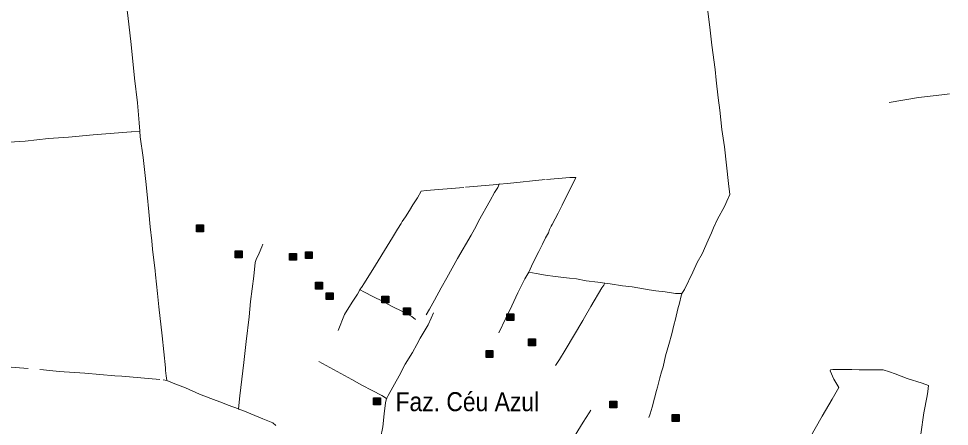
# Model space of a CAD drawing. Extents: x 393.5 to 446.9, y 8064.8 to 8120.4.
# Drawn here: x 425 to 432.83, y 8082.75 to 8086.18 of the extents above; entities that cross this region are included whole.
import ezdxf

# ---------------------------------------------------------------- set-up
doc = ezdxf.new("R2010")
doc.units = 0
doc.header["$LTSCALE"] = 0.064
doc.linetypes.add('DOT_DASHED', pattern=[7.7, 5, -1.2, 0.3, -1.2])
doc.layers.add('2', color=7, linetype='Continuous', lineweight=25)
doc.layers.add('22', color=7, linetype='DOT_DASHED', lineweight=13)
doc.layers.add('61', color=7, linetype='Continuous')

msp = doc.modelspace()

# ---------------------------------------------------------------- hatches: boundary and pattern name
at = {"layer": '2'}
for points in [[(426.4934, 8084.4448), (426.5514, 8084.4448), (426.5514, 8084.3868), (426.4934, 8084.3868)], [(426.8194, 8084.2253), (426.8774, 8084.2253), (426.8774, 8084.1673), (426.8194, 8084.1673)], [(427.4108, 8084.2181), (427.4688, 8084.2181), (427.4688, 8084.1601), (427.4108, 8084.1601)], [(427.278, 8084.2044), (427.336, 8084.2044), (427.336, 8084.1464), (427.278, 8084.1464)], [(427.4963, 8083.9617), (427.5543, 8083.9617), (427.5543, 8083.9037), (427.4963, 8083.9037)], [(427.5859, 8083.8732), (427.6439, 8083.8732), (427.6439, 8083.8152), (427.5859, 8083.8152)], [(428.0558, 8083.8447), (428.1138, 8083.8447), (428.1138, 8083.7867), (428.0558, 8083.7867)], [(428.2381, 8083.746), (428.2961, 8083.746), (428.2961, 8083.688), (428.2381, 8083.688)], [(429.1079, 8083.6957), (429.1659, 8083.6957), (429.1659, 8083.6377), (429.1079, 8083.6377)], [(429.2902, 8083.4845), (429.3482, 8083.4845), (429.3482, 8083.4265), (429.2902, 8083.4265)], [(428.9324, 8083.3864), (428.9904, 8083.3864), (428.9904, 8083.3284), (428.9324, 8083.3284)], [(427.9852, 8082.9864), (428.0432, 8082.9864), (428.0432, 8082.9284), (427.9852, 8082.9284)], [(429.9762, 8082.9605), (430.0342, 8082.9605), (430.0342, 8082.9025), (429.9762, 8082.9025)], [(430.5006, 8082.8458), (430.5586, 8082.8458), (430.5586, 8082.7878), (430.5006, 8082.7878)]]:
    msp.add_hatch(color=256, dxfattribs=at).paths.add_polyline_path(points)

# ---------------------------------------------------------------- linework, layer by layer
for points in [[(426.4934, 8084.4448), (426.5514, 8084.4448), (426.5514, 8084.3868), (426.4934, 8084.3868)], [(426.8194, 8084.2253), (426.8774, 8084.2253), (426.8774, 8084.1673), (426.8194, 8084.1673)], [(427.4108, 8084.2181), (427.4688, 8084.2181), (427.4688, 8084.1601), (427.4108, 8084.1601)], [(427.278, 8084.2044), (427.336, 8084.2044), (427.336, 8084.1464), (427.278, 8084.1464)], [(427.4963, 8083.9617), (427.5543, 8083.9617), (427.5543, 8083.9037), (427.4963, 8083.9037)], [(427.5859, 8083.8732), (427.6439, 8083.8732), (427.6439, 8083.8152), (427.5859, 8083.8152)], [(428.0558, 8083.8447), (428.1138, 8083.8447), (428.1138, 8083.7867), (428.0558, 8083.7867)], [(428.2381, 8083.746), (428.2961, 8083.746), (428.2961, 8083.688), (428.2381, 8083.688)], [(429.1079, 8083.6957), (429.1659, 8083.6957), (429.1659, 8083.6377), (429.1079, 8083.6377)], [(429.2902, 8083.4845), (429.3482, 8083.4845), (429.3482, 8083.4265), (429.2902, 8083.4265)], [(428.9324, 8083.3864), (428.9904, 8083.3864), (428.9904, 8083.3284), (428.9324, 8083.3284)], [(427.9852, 8082.9864), (428.0432, 8082.9864), (428.0432, 8082.9284), (427.9852, 8082.9284)], [(429.9762, 8082.9605), (430.0342, 8082.9605), (430.0342, 8082.9025), (429.9762, 8082.9025)], [(430.5006, 8082.8458), (430.5586, 8082.8458), (430.5586, 8082.7878), (430.5006, 8082.7878)]]:
    msp.add_lwpolyline(points, close=True, dxfattribs=at)
at = {"layer": '22'}
for points in [[(426.0169, 8085.2329), (426.0107, 8085.3049), (425.9956, 8085.4717), (425.9715, 8085.681), (425.9428, 8085.9657), (425.9141, 8086.2093), (425.8809, 8086.4984), (425.8628, 8086.6096), (425.8553, 8086.6857), (425.8419, 8086.8395), (425.8376, 8086.8682)], [(430.5821, 8083.8659), (430.6038, 8083.9012), (430.6748, 8084.0471), (430.7111, 8084.1289), (430.7532, 8084.2008), (430.8026, 8084.3149), (430.8324, 8084.3769), (430.8483, 8084.4199), (430.8788, 8084.4861), (430.9441, 8084.6045), (430.9601, 8084.644), (430.9862, 8084.7018), (430.9732, 8084.792), (430.9398, 8085.1023), (430.9194, 8085.2474), (430.9021, 8085.4102), (430.8875, 8085.5145), (430.8701, 8085.6639), (430.8614, 8085.7529), (430.8338, 8085.9601), (430.8208, 8086.0855), (430.799, 8086.2467)], [(432.3276, 8085.4753), (432.5737, 8085.5173), (432.7948, 8085.5436), (432.8345, 8085.5497)], [(423.3119, 8085.0017), (423.76, 8085.0415), (423.9832, 8085.0576), (424.318, 8085.0919), (424.6315, 8085.116), (424.8253, 8085.135), (425.0515, 8085.1511), (425.246, 8085.1716), (425.4167, 8085.1846), (425.6248, 8085.2036), (425.9475, 8085.2299), (426.015, 8085.2328), (426.0154, 8085.2328), (426.0169, 8085.2329)], [(426.1443, 8084.0569), (426.1224, 8084.2392), (426.1179, 8084.3109), (426.1042, 8084.428), (426.0922, 8084.5538), (426.0771, 8084.7016), (426.0665, 8084.8099), (426.0453, 8085.0111), (426.0197, 8085.186), (426.0169, 8085.2329)], [(429.0433, 8084.7872), (429.112, 8084.7941), (429.4425, 8084.8269), (429.6371, 8084.8452), (429.6894, 8084.8452), (429.6531, 8084.7677), (429.611, 8084.6874), (429.5732, 8084.6113), (429.5384, 8084.5422), (429.4897, 8084.4478), (429.4821, 8084.4331)], [(427.8693, 8083.8992), (427.8828, 8083.9182), (427.9075, 8083.9571), (428.0022, 8084.1048), (428.1005, 8084.2657), (428.1456, 8084.3376), (428.1862, 8084.4081), (428.2182, 8084.456), (428.2269, 8084.4729), (428.253, 8084.5138), (428.2864, 8084.5659), (428.3155, 8084.6138), (428.3547, 8084.673), (428.3867, 8084.728), (428.4273, 8084.7336), (428.7584, 8084.7618), (428.9933, 8084.7829), (429.0433, 8084.7872)], [(428.4289, 8083.6879), (428.4562, 8083.7358), (428.4968, 8083.8105), (428.5535, 8083.9148), (428.6029, 8083.9979), (428.6922, 8084.16), (428.8062, 8084.3587), (428.8483, 8084.4348), (428.8686, 8084.4757), (428.9681, 8084.649), (429.0044, 8084.7181), (429.0328, 8084.759), (429.0433, 8084.7872), (429.0438, 8084.7885), (429.0444, 8084.79)], [(429.4821, 8084.4331), (429.4681, 8084.4061), (429.458, 8084.3779), (429.4333, 8084.3356), (429.4086, 8084.2821), (429.3766, 8084.2215), (429.3258, 8084.1228), (429.2939, 8084.0475)], [(426.8467, 8082.8948), (426.8591, 8083.0032), (426.892, 8083.2857), (426.9118, 8083.4618), (426.9365, 8083.67), (426.9496, 8083.8002), (426.976, 8084.0131), (426.9892, 8084.1268), (426.9975, 8084.154), (427.0204, 8084.2075), (427.0435, 8084.2603), (427.0534, 8084.2811)], [(426.2327, 8083.2385), (426.2324, 8083.2414), (426.2039, 8083.51), (426.1768, 8083.7528), (426.1641, 8083.8663), (426.1487, 8084.0249), (426.1443, 8084.0569)], [(429.0387, 8083.5354), (429.0991, 8083.6597), (429.1502, 8083.7634), (429.2014, 8083.8717), (429.2602, 8083.9889), (429.2939, 8084.0475)], [(429.2939, 8084.0475), (429.3541, 8084.0362), (429.434, 8084.0221), (429.5139, 8084.0108), (429.6345, 8083.9967), (429.694, 8083.9897), (429.7762, 8083.974), (429.875, 8083.9613), (429.9331, 8083.9529)], [(427.6859, 8083.5549), (427.7405, 8083.6899), (427.8044, 8083.7928), (427.8494, 8083.8605), (427.8688, 8083.8982), (427.8693, 8083.8992)], [(428.3373, 8083.6465), (428.3069, 8083.673), (428.2343, 8083.7111), (428.1355, 8083.759), (428.0614, 8083.8013), (427.9845, 8083.8379), (427.9031, 8083.8802), (427.8729, 8083.8972), (427.8693, 8083.8992)], [(429.7616, 8083.6644), (429.8157, 8083.756), (429.9084, 8083.9148), (429.9229, 8083.9374), (429.9331, 8083.9529)], [(429.9331, 8083.9529), (429.9781, 8083.9473), (430.0827, 8083.9317), (430.164, 8083.9219), (430.3055, 8083.8983), (430.3636, 8083.8898), (430.4421, 8083.8814), (430.5269, 8083.8659), (430.5821, 8083.8659)], [(430.445, 8083.3412), (430.4724, 8083.4375), (430.4957, 8083.5263), (430.5145, 8083.5996), (430.5269, 8083.6503), (430.5487, 8083.7363), (430.5617, 8083.7842), (430.5763, 8083.8462), (430.5812, 8083.8629), (430.5813, 8083.8631), (430.5821, 8083.8659)], [(428.0968, 8082.9854), (428.107, 8083.0081), (428.1999, 8083.1728), (428.252, 8083.27), (428.3124, 8083.3698), (428.3494, 8083.4377), (428.3771, 8083.4902), (428.4438, 8083.6021), (428.4712, 8083.6594), (428.4904, 8083.7033)], [(429.5179, 8083.2585), (429.5496, 8083.311), (429.5992, 8083.3895), (429.747, 8083.6396), (429.7472, 8083.64), (429.7616, 8083.6644)], [(424.344, 8083.2805), (424.4806, 8083.2835), (424.7568, 8083.2588), (425.2055, 8083.2244), (425.3382, 8083.2103), (425.5526, 8083.1953), (425.8052, 8083.1741), (425.8651, 8083.1688), (426.2122, 8083.1398), (426.245, 8083.1336)], [(427.5251, 8083.2923), (427.8022, 8083.1425), (427.887, 8083.0937), (427.9719, 8083.05), (428.0533, 8083.0064), (428.0949, 8082.9812), (428.0968, 8082.9854)], [(430.3884, 8083.1219), (430.3956, 8083.1565), (430.4101, 8083.2073), (430.4232, 8083.2496), (430.445, 8083.3412)], [(426.245, 8083.1336), (426.2395, 8083.1733), (426.2329, 8083.2165), (426.2327, 8083.2385)], [(432.0748, 8083.2229), (432.0124, 8083.225), (431.8516, 8083.2263), (431.8325, 8083.2226), (431.8299, 8083.2151), (431.8605, 8083.1458), (431.9039, 8083.0752), (431.8464, 8082.9759), (431.7634, 8082.833), (431.6565, 8082.644)], [(432.6523, 8083.0407), (432.6599, 8083.0914), (432.6051, 8083.11), (432.48, 8083.1508), (432.3767, 8083.1892), (432.3308, 8083.2065), (432.2758, 8083.2222), (432.1625, 8083.2222), (432.0748, 8083.2229)], [(426.7118, 8082.9466), (426.6157, 8082.9812), (426.5183, 8083.0196), (426.4012, 8083.0709), (426.3104, 8083.1045), (426.245, 8083.1336)], [(430.3041, 8082.8216), (430.3143, 8082.8512), (430.3317, 8082.9089), (430.3506, 8082.9836), (430.368, 8083.0485), (430.3756, 8083.0773), (430.3883, 8083.1213), (430.3884, 8083.1219)], [(432.5043, 8082.0658), (432.5131, 8082.167), (432.5373, 8082.3168), (432.5564, 8082.4481), (432.5812, 8082.5861), (432.594, 8082.6814), (432.6202, 8082.8604), (432.6463, 8083.0033), (432.6523, 8083.0407)], [(428.0291, 8082.4962), (428.0447, 8082.6485), (428.0637, 8082.7443), (428.0741, 8082.8518), (428.0845, 8082.9442), (428.0949, 8082.9811), (428.0949, 8082.9812)], [(426.8467, 8082.8948), (426.7601, 8082.9267), (426.7118, 8082.9466)], [(427.1613, 8082.7531), (427.1354, 8082.7779), (427.0529, 8082.8115), (426.883, 8082.8804), (426.8505, 8082.8933), (426.8481, 8082.8942), (426.8467, 8082.8948)], [(429.3816, 8082.1904), (429.4327, 8082.2714), (429.4986, 8082.3764), (429.6304, 8082.5867), (429.7505, 8082.7831), (429.8016, 8082.8612), (429.8157, 8082.8835)]]:
    msp.add_lwpolyline(points, dxfattribs=at)

# ---------------------------------------------------------------- texts
at = {"layer": '61', "width": 0.9}
msp.add_text('Faz. Céu Azul', height=0.16, dxfattribs=at).set_placement((428.17, 8082.875))

doc.saveas('drawing.dxf')
